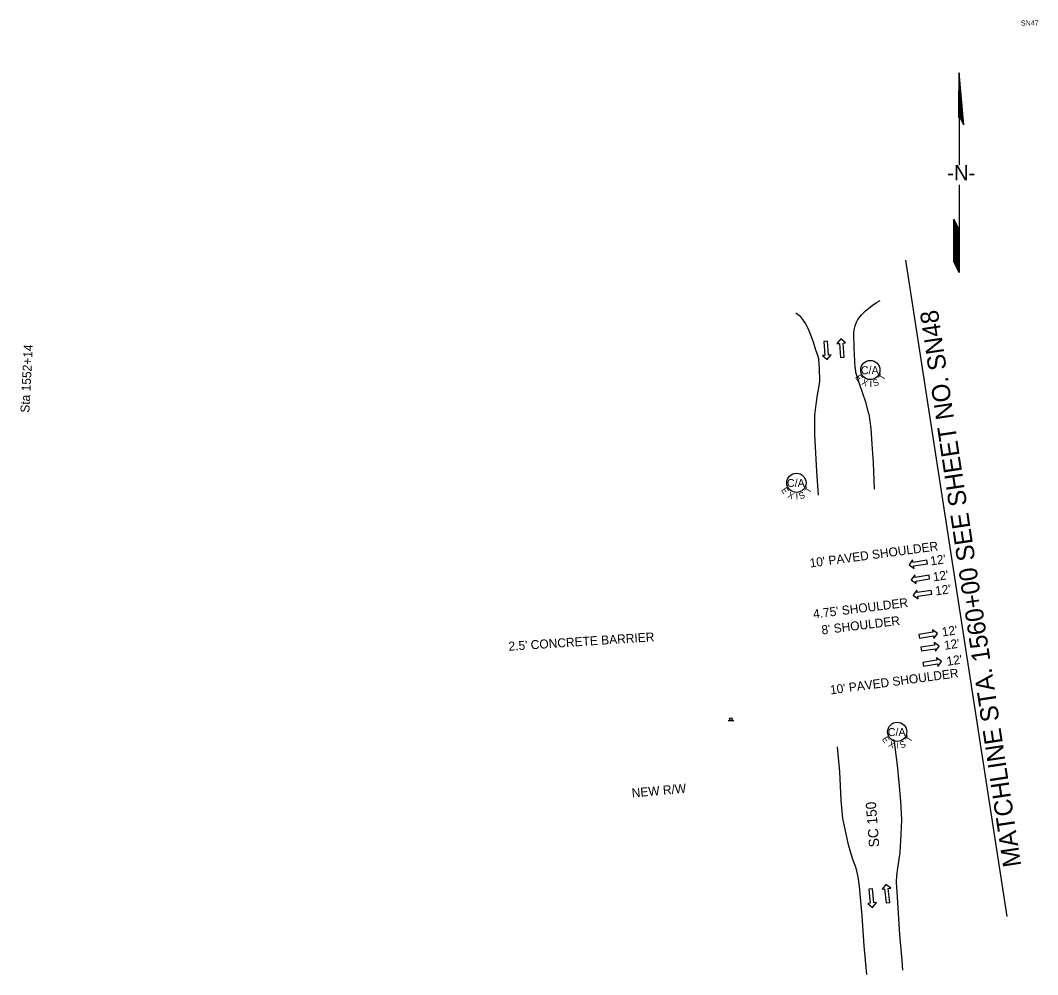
# Model space of a CAD drawing. Extents: x 1801862 to 1803462, y 1187717 to 1188466.
# Drawn here: x 1802668 to 1803462, y 1187717 to 1188463 of the extents above; entities that cross this region are included whole.
import ezdxf

# ---------------------------------------------------------------- set-up
doc = ezdxf.new("R2010")
doc.units = 0
for name, color, linetype in [('RD_EX_BldgApp', 7, 'Continuous'), ('RD_EX_Road', 7, 'Continuous'), ('RD_PD_Final_LnLine', 7, 'Continuous'), ('RD_PD_Final_TX', 7, 'Continuous'), ('RD_PD_RW_TX', 7, 'Continuous'), ('RD_SHT_MatchLine', 7, 'Continuous'), ('RD_SHT_TX', 7, 'Continuous'), ('RD_Sketch1', 7, 'Continuous'), ('RD_Sketch8', 7, 'Continuous'), ('RD_TX_RoadID', 7, 'Continuous'), ('SN_P_Signs', 7, 'Continuous')]:
    doc.layers.add(name, color=color, linetype=linetype)

# ---------------------------------------------------------------- blocks, each defined once
blk = doc.blocks.new('SARRW2')
at = {"layer": 'RD_PD_Final_LnLine'}
blk.add_lwpolyline([(-12, 1.2), (-12, -1.2), (-2.83, -1.2), (-2.83, -2.83), (0, 0), (-2.83, 2.83), (-2.83, 1.2)], close=True, dxfattribs=at)

msp = doc.modelspace()

# ---------------------------------------------------------------- linework, layer by layer
at = {"layer": 'RD_EX_BldgApp'}
msp.add_line((1803220.56, 1187916.02), (1803225.06, 1187916.02), dxfattribs=at)
msp.add_circle((1803222.82, 1187917.03), 1, dxfattribs=at)
at = {"layer": 'RD_EX_Road'}
for points in [[(1803330.56, 1188155.5), (1803328.13, 1188164.7), (1803323.55, 1188178.2), (1803321.37, 1188184.77), (1803320.5, 1188187.95), (1803320.01, 1188191.2), (1803319.99, 1188191.48), (1803319.16, 1188207.21), (1803318.71, 1188218.09), (1803319.04, 1188221.21), (1803319.76, 1188224.26), (1803320.85, 1188227.19), (1803321.93, 1188229.32), (1803324.85, 1188232.77), (1803328.05, 1188235.94), (1803331.52, 1188238.82), (1803333.22, 1188240.06), (1803336.56, 1188242.48), (1803339.27, 1188244.06)], [(1803273.53, 1188234.57), (1803276.31, 1188232.24), (1803278.84, 1188229.18), (1803281.05, 1188225.89), (1803282.92, 1188222.39), (1803284.24, 1188219.27), (1803287.06, 1188211.73), (1803288.98, 1188205.5), (1803290.23, 1188202.22), (1803291.1, 1188198.81), (1803291.33, 1188197.48), (1803291.71, 1188191.38), (1803292.01, 1188180.92), (1803291.19, 1188175.79), (1803290.31, 1188170.49), (1803289.2, 1188162.71), (1803288.18, 1188154.47), (1803288.21, 1188152.13)], [(1803330.56, 1188155.5), (1803332.1, 1188144.08), (1803332.83, 1188131.8), (1803333.93, 1188117.32), (1803334.74, 1188096.77)], [(1803288.21, 1188152.13), (1803288.05, 1188139.41), (1803289.64, 1188110.44), (1803290.85, 1188091.98)], [(1803350.11, 1187901.11), (1803352.55, 1187881.19), (1803353.99, 1187867.43), (1803355.4, 1187852.85), (1803356.04, 1187838.49), (1803355.54, 1187826.97), (1803354.64, 1187812.92), (1803352.85, 1187800.55), (1803352.21, 1187794.98), (1803351.97, 1187789.38), (1803351.97, 1187789.31), (1803352.57, 1187778.29), (1803354.55, 1187748.64), (1803356.19, 1187728.46), (1803356.8, 1187720.97)], [(1803328.89, 1187717.42), (1803326.96, 1187739.83), (1803325.31, 1187763.37), (1803323.35, 1187786.33), (1803322.12, 1187793.75), (1803320.64, 1187800.58), (1803317.71, 1187808.2), (1803314.71, 1187818.77), (1803312.02, 1187831.14), (1803310.14, 1187839.46), (1803309.04, 1187853.86), (1803307.79, 1187875.84), (1803306.09, 1187895.34)]]:
    msp.add_lwpolyline(points, dxfattribs=at)
at = {"layer": 'RD_SHT_MatchLine'}
msp.add_line((1803359.07, 1188275.71), (1803438.45, 1187762.8), dxfattribs=at)
at = {"layer": 'RD_Sketch1'}
for p, q in [((1803400.99, 1188421.95), (1803400.78, 1188386.79)), ((1803404.72, 1188381.25), (1803400.99, 1188421.95)), ((1803400.99, 1188387.08), (1803400.99, 1188365.26)), ((1803401.29, 1188388.19), (1803404.72, 1188381.25)), ((1803400.99, 1188365.26), (1803400.99, 1188349.79)), ((1803400.99, 1188334.34), (1803400.99, 1188308.57)), ((1803397, 1188293.51), (1803397, 1188307.68)), ((1803397, 1188307.68), (1803400.99, 1188299.12)), ((1803400.99, 1188308.57), (1803400.99, 1188266.05)), ((1803397, 1188274.61), (1803397, 1188293.51)), ((1803400.99, 1188266.05), (1803397, 1188274.61))]:
    msp.add_line(p, q, dxfattribs=at)
for points in [[(1803401, 1188387.39), (1803401, 1188421.83)], [(1803401.1, 1188387.65), (1803401.1, 1188420.8)], [(1803401.19, 1188387.91), (1803401.19, 1188419.77)], [(1803401.29, 1188388.17), (1803401.29, 1188418.73)], [(1803401.38, 1188388.02), (1803401.38, 1188417.7)], [(1803401.47, 1188387.83), (1803401.47, 1188416.67)], [(1803401.57, 1188387.64), (1803401.57, 1188415.64)], [(1803401.66, 1188387.44), (1803401.66, 1188414.6)], [(1803401.76, 1188387.25), (1803401.76, 1188413.57)], [(1803401.85, 1188387.06), (1803401.85, 1188412.54)], [(1803401.95, 1188386.87), (1803401.95, 1188411.51)], [(1803402.04, 1188386.68), (1803402.04, 1188410.47)], [(1803400.91, 1188387.13), (1803400.91, 1188407.92)], [(1803402.14, 1188386.48), (1803402.14, 1188409.44)], [(1803402.23, 1188386.29), (1803402.23, 1188408.41)], [(1803402.33, 1188386.1), (1803402.33, 1188407.38)], [(1803402.42, 1188385.91), (1803402.42, 1188406.34)], [(1803402.51, 1188385.72), (1803402.51, 1188405.31)], [(1803402.61, 1188385.53), (1803402.61, 1188404.28)], [(1803402.7, 1188385.33), (1803402.7, 1188403.25)], [(1803402.8, 1188385.14), (1803402.8, 1188402.21)], [(1803402.89, 1188384.95), (1803402.89, 1188401.18)], [(1803402.99, 1188384.76), (1803402.99, 1188400.15)], [(1803403.08, 1188384.57), (1803403.08, 1188399.12)], [(1803403.18, 1188384.38), (1803403.18, 1188398.08)], [(1803403.27, 1188384.18), (1803403.27, 1188397.05)], [(1803403.36, 1188383.99), (1803403.36, 1188396.02)], [(1803403.46, 1188383.8), (1803403.46, 1188394.99)], [(1803403.55, 1188383.61), (1803403.55, 1188393.95)], [(1803400.81, 1188386.87), (1803400.81, 1188392.01)], [(1803403.65, 1188383.42), (1803403.65, 1188392.92)], [(1803403.74, 1188383.23), (1803403.74, 1188391.89)], [(1803403.84, 1188383.03), (1803403.84, 1188390.86)], [(1803403.93, 1188382.84), (1803403.93, 1188389.82)], [(1803404.03, 1188382.65), (1803404.03, 1188388.79)], [(1803404.12, 1188382.46), (1803404.12, 1188387.76)], [(1803404.22, 1188382.27), (1803404.22, 1188386.73)], [(1803404.31, 1188382.08), (1803404.31, 1188385.69)], [(1803404.4, 1188381.88), (1803404.4, 1188384.66)], [(1803404.5, 1188381.69), (1803404.5, 1188383.63)], [(1803404.59, 1188381.5), (1803404.59, 1188382.6)], [(1803404.69, 1188381.31), (1803404.69, 1188381.56)], [(1803397.08, 1188274.45), (1803397.08, 1188307.52)], [(1803397.17, 1188274.24), (1803397.17, 1188307.31)], [(1803397.26, 1188274.04), (1803397.26, 1188307.11)], [(1803397.36, 1188273.84), (1803397.36, 1188306.91)], [(1803397.45, 1188273.64), (1803397.45, 1188306.71)], [(1803397.55, 1188273.43), (1803397.55, 1188306.5)], [(1803397.64, 1188273.23), (1803397.64, 1188306.3)], [(1803397.74, 1188273.03), (1803397.74, 1188306.1)], [(1803397.83, 1188272.83), (1803397.83, 1188305.9)], [(1803397.93, 1188272.62), (1803397.93, 1188305.69)], [(1803398.02, 1188272.42), (1803398.02, 1188305.49)], [(1803398.11, 1188272.22), (1803398.11, 1188305.29)], [(1803398.21, 1188272.02), (1803398.21, 1188305.09)], [(1803398.3, 1188271.81), (1803398.3, 1188304.88)], [(1803398.4, 1188271.61), (1803398.4, 1188304.68)], [(1803398.49, 1188271.41), (1803398.49, 1188304.48)], [(1803398.59, 1188271.2), (1803398.59, 1188304.28)], [(1803398.68, 1188271), (1803398.68, 1188304.07)], [(1803398.78, 1188270.8), (1803398.78, 1188303.87)], [(1803398.87, 1188270.6), (1803398.87, 1188303.67)], [(1803398.96, 1188270.39), (1803398.96, 1188303.46)], [(1803399.06, 1188270.19), (1803399.06, 1188303.26)], [(1803399.15, 1188269.99), (1803399.15, 1188303.06)], [(1803399.25, 1188269.79), (1803399.25, 1188302.86)], [(1803399.34, 1188269.58), (1803399.34, 1188302.65)], [(1803399.44, 1188269.38), (1803399.44, 1188302.45)], [(1803399.53, 1188269.18), (1803399.53, 1188302.25)], [(1803399.63, 1188268.98), (1803399.63, 1188302.05)], [(1803399.72, 1188268.77), (1803399.72, 1188301.84)], [(1803399.82, 1188268.57), (1803399.82, 1188301.64)], [(1803399.91, 1188268.37), (1803399.91, 1188301.44)], [(1803400, 1188268.17), (1803400, 1188301.24)], [(1803400.1, 1188267.96), (1803400.1, 1188301.03)], [(1803400.19, 1188267.76), (1803400.19, 1188300.83)], [(1803400.29, 1188267.56), (1803400.29, 1188300.63)], [(1803400.38, 1188267.35), (1803400.38, 1188300.43)], [(1803400.48, 1188267.15), (1803400.48, 1188300.22)], [(1803400.57, 1188266.95), (1803400.57, 1188300.02)], [(1803400.67, 1188266.75), (1803400.67, 1188299.82)], [(1803400.76, 1188266.54), (1803400.76, 1188299.61)], [(1803400.85, 1188266.34), (1803400.85, 1188299.41)], [(1803400.95, 1188266.14), (1803400.95, 1188299.21)]]:
    msp.add_lwpolyline(points, dxfattribs=at)
at = {"layer": 'RD_Sketch8'}
for centre in [(1803331.71, 1188189.8), (1803273.97, 1188101.66), (1803352.73, 1187907.11)]:
    msp.add_circle(centre, 7.5, dxfattribs=at)
at = {"layer": 'SN_P_Signs'}
msp.add_line((1803220.56, 1187916.02), (1803225.06, 1187916.02), dxfattribs=at)
msp.add_circle((1803222.82, 1187917.03), 1, dxfattribs=at)

# ---------------------------------------------------------------- block references
at = {"layer": 'RD_PD_Final_LnLine'}
for p, xscale, yscale, rotation in [((1803297.93, 1188197.91), 1.2000000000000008, 1.200000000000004, -85.61759197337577), ((1803308.75, 1188214.03), 1.2000000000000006, 1.2000000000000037, 94.38240802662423), ((1803361.93, 1188037.54), 1.1999999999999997, 1.2000000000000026, -170.73306467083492), ((1803363.59, 1188025.81), 1.1999999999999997, 1.2000000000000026, -170.73306467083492), ((1803365.29, 1188013.87), 1.1999999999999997, 1.2000000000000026, -170.73306467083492), ((1803384.11, 1187984.05), 1.2, 1.2000000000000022, 9.266935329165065), ((1803385.53, 1187974.05), 1.2, 1.2000000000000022, 9.266935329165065), ((1803387.22, 1187962.18), 1.2, 1.2000000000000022, 9.266935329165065), ((1803333.52, 1187769.99), 1.2000000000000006, 1.2000000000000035, -83.42774024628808), ((1803343.87, 1187787.93), 1.2000000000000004, 1.2000000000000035, 96.57225975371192)]:
    msp.add_blockref('SARRW2', p, dxfattribs=dict(at, xscale=xscale, yscale=yscale, rotation=rotation))

# ---------------------------------------------------------------- texts
at = {"layer": 'RD_PD_Final_TX'}
for s, rotation, p in [("10' PAVED SHOULDER", 7.65303, (1803284.79, 1188035.47)), ("12'", 8.64011, (1803379.07, 1188037.04)), ("12'", 8.64011, (1803381.09, 1188024.63)), ("12'", 8.64011, (1803382.89, 1188013.62)), ("4.75' SHOULDER", 7.07049, (1803287.43, 1187995.62)), ("8' SHOULDER", 7.07049, (1803294.01, 1187983.16)), ("12'", 8.64011, (1803388.12, 1187981.56)), ("2.5' CONCRETE BARRIER", 3.75887, (1803049.31, 1187970.44)), ("12'", 8.64011, (1803389.83, 1187971.11)), ("12'", 8.64011, (1803391.82, 1187958.65)), ("10' PAVED SHOULDER", 7.65303, (1803300.72, 1187936.31))]:
    msp.add_text(s, height=7, rotation=rotation, dxfattribs=at).set_placement(p)
at = {"layer": 'RD_PD_RW_TX'}
msp.add_text('NEW R/W', height=7, rotation=5.14532, dxfattribs=at).set_placement((1803145.65, 1187855.81))
at = {"layer": 'RD_SHT_TX'}
for s, height, rotation, p in [('SN47', 4, 0.54365, (1803449.33, 1188458.82)), ('MATCHLINE STA. 1560+00 SEE SHEET NO. SN48', 14.1726, 98.53928, (1803449.64, 1187802.53))]:
    msp.add_text(s, height=height, rotation=rotation, dxfattribs=at).set_placement(p)
at = {"layer": 'RD_Sketch1'}
msp.add_text('-N-', height=11.811, rotation=0, dxfattribs=at).set_placement((1803391.8, 1188338.05))
at = {"layer": 'RD_Sketch8'}
for s, height, rotation, p in [('C/A', 6.25, 0.54365, (1803324.33, 1188186.45)), ('T', 5, 58.7288, (1803341.99, 1188181.19)), ('E', 5, 303.7549, (1803319.54, 1188184.17)), ('X', 5, 336.18427, (1803324.38, 1188178.56)), ('I', 5, 0.34427, (1803331.18, 1188176.55)), ('S', 5, 22.3361, (1803334.83, 1188176.76)), ('C/A', 6.25, 0.54365, (1803266.59, 1188098.32)), ('E', 5, 303.7549, (1803261.8, 1188096.03)), ('X', 5, 336.18427, (1803266.64, 1188090.42)), ('I', 5, 0.34427, (1803273.44, 1188088.41)), ('S', 5, 22.3361, (1803277.09, 1188088.62)), ('T', 5, 58.7288, (1803284.24, 1188093.05)), ('C/A', 6.25, 0.54365, (1803345.35, 1187903.76)), ('E', 5, 303.7549, (1803340.56, 1187901.47)), ('T', 5, 58.7288, (1803363.01, 1187898.5)), ('X', 5, 336.18427, (1803345.4, 1187895.87)), ('I', 5, 0.34427, (1803352.2, 1187893.86)), ('S', 5, 22.3361, (1803355.85, 1187894.07))]:
    msp.add_text(s, height=height, rotation=rotation, dxfattribs=at).set_placement(p)
at = {"layer": 'RD_TX_RoadID'}
msp.add_text('SC 150', height=8, rotation=94.45863, dxfattribs=at).set_placement((1803338.77, 1187817.23))
at = {"layer": 'SN_P_Signs'}
msp.add_text('Sta 1552+14', height=7, rotation=86.99992, dxfattribs=at).set_placement((1802674.8, 1188156.3))

doc.saveas('drawing.dxf')
